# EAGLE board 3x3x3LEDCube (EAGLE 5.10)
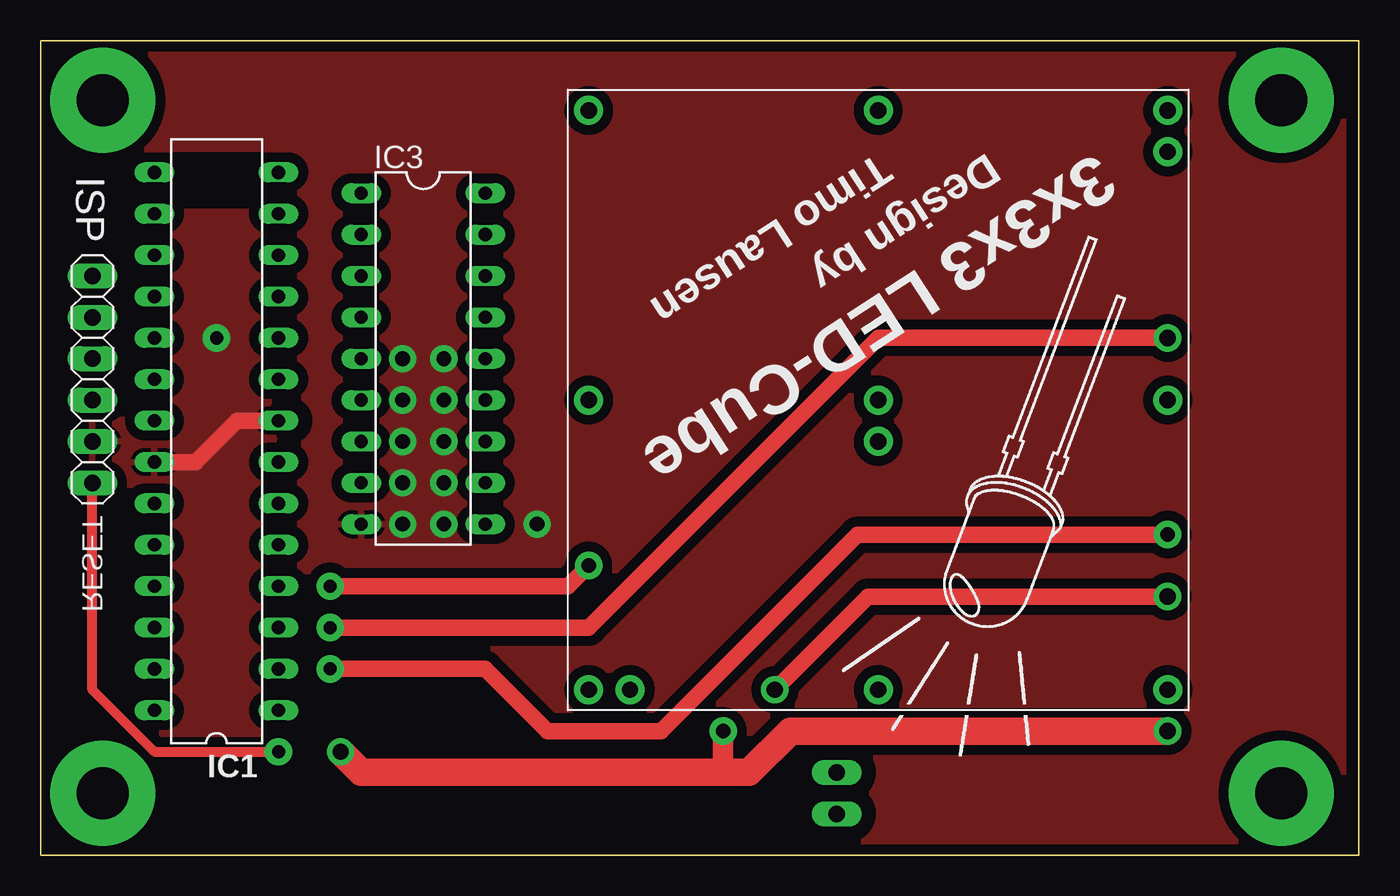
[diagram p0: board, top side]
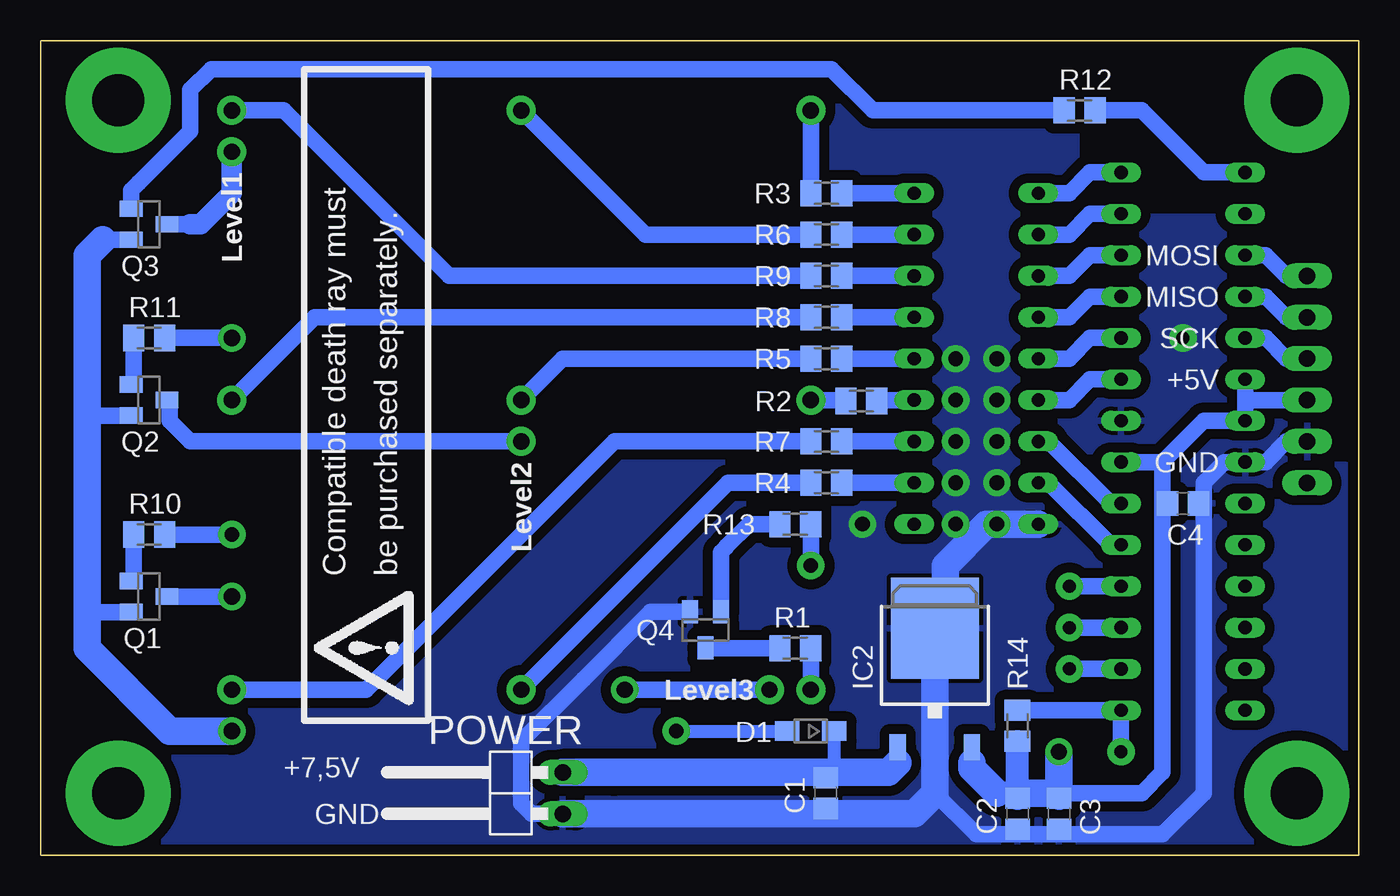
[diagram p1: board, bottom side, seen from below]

Size 80.95 x 50 mm. Coordinates in mm from the lower left corner, seen from the top.
Outline: 0,0 80,0
Outline: 80,50 0,50
Outline: 0,50 80.95,50 80.95,0 0,0
Outline: 0,0 0,50
Copper layers (1*2*15*16): Top 0.035mm / dielectric 0.2mm / Route2 0.0175mm / dielectric 1.1mm / Route15 0.0175mm / dielectric 0.2mm / Bottom 0.035mm
Design rules "SeeedStudio_DRU_no_angle_20130527 *": minimum track width 6mil, minimum drill 12mil, track to track 6mil, track to pad 6mil, pad to pad 6mil, via to via 6mil, smd to smd 0mil, copper to edge 10mil, drill to drill 10mil, minimum pad ring 6mil, minimum via ring 6mil, stop-mask expansion 2mil, vias tented up to drill 25mil, thermal gap 10mil
tRestrict: area 47.3,1.6 to 50.5,3.5; area 47.3,4.1 to 50.5,6; area 14.9,26 to 15.9,27.3; area 0.6,24.8 to 1.9,26; area 8.3,40.3 to 13.7,42.5
bRestrict: area 10.8,42.5 to 16.5,45.1; area 8.3,40 to 13.3,43.2; area 0.6,24.8 to 1.9,26

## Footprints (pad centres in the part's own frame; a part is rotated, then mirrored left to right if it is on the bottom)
C0805 = smd 1.3 x 1.5: 1 -0.95,0; 2 0.95,0
SOD323-W = smd 1.5 x 1.2: A 1.45,0; C -1.45,0
DIL28-3 = drill 0.813 long: 1 -16.51,-3.81; 2 -13.97,-3.81; 3 -11.43,-3.81; 4 -8.89,-3.81; 5 -6.35,-3.81; 6 -3.81,-3.81; 7 -1.27,-3.81; 8 1.27,-3.81; 9 3.81,-3.81; 10 6.35,-3.81; 11 8.89,-3.81; 12 11.43,-3.81; 13 13.97,-3.81; 14 16.51,-3.81; 15 16.51,3.81; 16 13.97,3.81; 17 11.43,3.81; 18 8.89,3.81; 19 6.35,3.81; 20 3.81,3.81; 21 1.27,3.81; 22 -1.27,3.81; 23 -3.81,3.81; 24 -6.35,3.81; 25 -8.89,3.81; 26 -11.43,3.81; 27 -13.97,3.81; 28 -16.51,3.81
TO252 = smd 1 x 1.6: 1 -2.28,-4.8; 2 2.28,-4.8 | smd 5.4 x 6.2: 3 0,2.5
DIL18 = drill 0.813 long: 1 -10.16,-3.81; 2 -7.62,-3.81; 3 -5.08,-3.81; 4 -2.54,-3.81; 5 0,-3.81; 6 2.54,-3.81; 7 5.08,-3.81; 8 7.62,-3.81; 9 10.16,-3.81; 10 10.16,3.81; 11 7.62,3.81; 12 5.08,3.81; 13 2.54,3.81; 14 0,3.81; 15 -2.54,3.81; 16 -5.08,3.81; 17 -7.62,3.81; 18 -10.16,3.81
1X06 = drill 1.016 long: 1 -6.35,0; 2 -3.81,0; 3 -1.27,0; 4 1.27,0; 5 3.81,0; 6 6.35,0
1X02/90 = drill 1.016 long: 1 -1.27,-3.81; 2 1.27,-3.81
SOT23 = smd 1 x 1.4: 1 -0.95,-1.1; 2 0.95,-1.1; 3 0,1.1
M0805 = smd 1.3 x 1.6: 1 -0.95,0; 2 0.95,0
CUBEPAD = drill 1 pad 1.778 round: EBENE1 2.54,0; EBENE2 17.78,15.24; EBENE3 35.56,33.02; LED1 0,0; LED2 0,17.78; LED3 0,35.56; LED4 17.78,0; LED5 17.78,17.78; LED6 17.78,35.56; LED7 35.56,0; LED8 35.56,17.78; LED9 35.56,35.56

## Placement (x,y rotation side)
C1  [C0805]  32.75,3.81 90 bottom
C2  [C0805]  20.95,2.54 90 bottom
C3  [C0805]  18.41,2.54 90 bottom
C4  100n  [C0805]  10.79,21.59 180 bottom
D1  1N4148  [SOD323-W]  33.66,7.62 180 bottom
IC1  MEGA8-P  [DIL28-3]  10.79,25.4 90 top
IC2  78M05  [TO252]  26.04,11.43 0 bottom
IC3  [DIL18]  23.5,30.48 270 top
ISP  [1X06]  3.17,29.21 270 top
POWER  [1X02/90]  52.7,3.81 90 bottom
Q1  SI2301  [SOT23]  74.3,15.88 270 bottom
Q2  SI2301  [SOT23]  74.3,27.94 270 bottom
Q3  SI2301  [SOT23]  74.3,38.73 270 bottom
Q4  IRLML 2502  [SOT23]  40.12,13.84 180 bottom
R1  [M0805]  34.61,12.7 180 bottom
R2  [M0805]  30.55,27.88 0 bottom
R3  [M0805]  32.7,40.64 0 bottom
R4  [M0805]  32.7,22.86 0 bottom
R5  [M0805]  32.7,30.48 0 bottom
R6  [M0805]  32.7,38.1 0 bottom
R7  [M0805]  32.7,25.4 0 bottom
R8  [M0805]  32.7,33.02 0 bottom
R9  [M0805]  32.7,35.56 0 bottom
R10  330R  [M0805]  74.3,19.68 0 bottom
R11  330R  [M0805]  74.3,31.75 0 bottom
R12  330R  [M0805]  17.14,45.72 0 bottom
R13  330R  [M0805]  34.61,20.32 0 bottom
R14  [M0805]  20.95,7.94 270 bottom
U$1  3X3X3LEDCUBE  [CUBEPAD]  33.66,10.16 0 top

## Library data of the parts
C1-C4 R1-R14 = rcl
D1 = diode
IC1 = atmel
IC2 = linear
IC3 = uln-udn
ISP POWER = pinhead
Q1-Q4 = transistor-small-signal
U$1 = zeug

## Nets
0V: C1.1 C2.1 C3.1 C4.1 IC1.8 IC1.22 IC2.3 IC3.9 ISP.5 POWER.1 Q4.2
+5V: C2.2 C3.2 C4.2 D1.A IC1.7 IC1.20 IC1.21 IC2.2 ISP.4 Q1.2 Q2.2 Q3.2 R14.2
CON_MISO: IC1.18 ISP.2
CON_MOSI: IC1.17 ISP.1
CON_RESET: IC1.1 ISP.6 R14.1
CON_SCK: IC1.19 ISP.3
DRAIN: Q4.3 R1.2
EBENE1: IC1.2 R10.2
EBENE2: IC1.3 R11.2
EBENE3: IC1.15 R12.2
GATE: Q4.1 R13.1
LED1: IC1.4 R13.2
LED2: IC1.9 IC3.6
LED3: IC1.14 IC3.1
LED4: IC1.5 IC3.8
LED5: IC1.10 IC3.5
LED6: IC1.13 IC3.2
LED7: IC1.6 IC3.7
LED8: IC1.11 IC3.4
LED9: IC1.12 IC3.3
N$1: Q1.3 U$1.EBENE1
N$2: Q2.3 U$1.EBENE2
N$3: Q3.3 U$1.EBENE3
N$4: IC3.15 R8.2
N$5: IC3.18 R3.2
N$6: IC3.17 R6.2
N$7: IC3.16 R9.2
N$8: IC3.13 R2.2
N$9: IC3.14 R5.2
N$10: IC3.12 R7.2
N$11: R1.1 U$1.LED1
N$16: IC3.11 R4.2
N$23: Q3.1 R12.1
N$24: Q2.1 R11.1
N$25: Q1.1 R10.1
N$32: R2.1 U$1.LED2
N$33: C1.2 D1.C IC2.1 POWER.2
N$34: R3.1 U$1.LED3
N$35: R4.1 U$1.LED4
N$36: R5.1 U$1.LED5
N$37: R6.1 U$1.LED6
N$38: R7.1 U$1.LED7
N$39: R8.1 U$1.LED8
N$40: R9.1 U$1.LED9

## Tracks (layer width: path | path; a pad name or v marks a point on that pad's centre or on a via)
0V  (via drill 0.8 pad 1.68, 0.9 pad 1.68)
  Top 1.016: IC1.8 12.06,26.67 9.53,24.13 IC1.22
  Bottom 0.406: 16.51,1.27 15.24,1.27
  Bottom 1.016: ISP.5 4.45,25.4 5.71,24.13 IC1.22 8.26,24.13 9.53,22.86 9.53,21.59 | 26.04,3.81 23.5,1.27 20.95,1.27 | 18.41,1.27 16.51,1.27 12.06,1.27 9.53,3.81 9.53,21.59 | 18.41,1.27 20.95,1.27 | 25.4,15.88 26.04,15.88 | 9.53,21.59 C4.1 | 18.41,1.27 C3.1 | 20.95,1.27 C2.1 | IC2.3 26.07,13.97 | Q4.2 43.48,14.94 47.62,10.79 51.44,6.99 51.44,3.17 50.8,2.54 POWER.1
  Bottom 1.27: C1.1 32.7,2.86 32.38,2.54
  Bottom 1.422: IC2.3 25.4,15.88
  Bottom 1.676: 25.4,15.88 25.4,17.78 22.86,20.32 v22.23,20.32 IC3.9 | IC2.3 26.04,3.81 27.3,2.54 32.38,2.54 45.72,2.54 POWER.1
  other vias: 24.77,20.32 22.23,25.4 24.77,25.4 22.23,22.86 24.77,22.86 30.48,20.32 22.23,27.94 24.77,27.94 22.23,30.48 24.77,30.48 10.79,31.75
  pour Bottom (isolate 0.61): 0,0 80.01,0 80.01,50.16 0,50.16
  pour Top (isolate 0.61): 0,50.16 80.01,50.16 80.01,0 0,0
+5V  (via drill 0.9 pad 1.68, 1 pad 1.68)
  Top 1.27: v41.91,7.62 41.91,6.67 41.91,5.08
  Top 1.676: v69.22,7.62 46.04,7.62 43.5,5.08 41.91,5.08 19.68,5.08 v18.41,6.35
  Bottom 0.254: 12.06,21.59 C4.2
  Bottom 0.813: v41.91,7.62 D1.A
  Bottom 1.016: 23.75,5.66 IC2.2 | 18.41,3.81 15.24,3.81 13.34,3.81 12.06,5.08 12.06,21.59 12.06,24.13 | 12.06,24.13 IC1.7 | 12.06,24.13 9.53,26.67 IC1.21 6.99,27.94 | 6.99,27.94 IC1.20 | 6.99,27.94 ISP.4 | 77.15,37.78 Q3.2 | Q2.2 78.11,26.99 78.11,27.94 | Q1.2 78.11,14.93 78.11,15.24
  Bottom 1.422: R14.2 C2.2 21.27,3.81 22.23,3.81 | 18.41,3.81 C3.2
  Bottom 1.676: 21.27,3.81 18.41,3.81 v18.41,6.35 | 23.75,5.66 23.75,5.34 22.23,3.81 | v69.22,7.62 73.03,7.62 78.11,12.7 78.11,15.24 78.11,27.94 78.11,34.29 78.11,36.2 78.11,36.83 77.15,37.78
CON_MISO
  Bottom 1.016: IC1.18 5.71,34.29 4.45,33.02 ISP.2
CON_MOSI
  Bottom 1.016: IC1.17 5.71,36.83 4.45,35.56 ISP.1
CON_RESET  (via drill 0.8 pad 1.68)
  Top 0.61: ISP.6 3.17,10.16 6.99,6.35 v14.61,6.35
  Bottom 0.61: R14.1
  Bottom 0.813: R14.1
  Bottom 1.016: R14.1 IC1.1 v14.61,6.35
CON_SCK
  Bottom 1.016: IC1.19 5.71,31.75 4.45,30.48 ISP.3
DRAIN
  Bottom 1.016: R1.2 38.1,12.7 40.12,12.7 Q4.3
EBENE1  (via drill 0.8 pad 1.68, 0.9 pad 1.68)
  Top 1.016: v69.22,19.68 50.16,19.68 38.1,7.62 31.11,7.62 27.3,11.43 v17.78,11.43
  Bottom 1.016: v69.22,19.68 R10.2 | IC1.2 v17.78,11.43
EBENE2  (via drill 0.8 pad 1.68, 1 pad 1.68)
  Top 1.016: v17.78,13.97 33.66,13.97 51.44,31.75 v69.22,31.75
  Bottom 1.016: v69.22,31.75 R11.2 | IC1.3 v17.78,13.97
EBENE3
  Bottom 1.016: IC1.15 9.53,41.91 13.34,45.72 R12.2
GATE
  Bottom 1.016: R13.1 37.47,20.32 38.83,18.95 38.88,18.91 39.17,18.61 Q4.1
LED1  (via drill 0.8 pad 1.68, 0.9 pad 1.68)
  Top 1.016: v33.66,17.78 32.38,16.51 v17.78,16.51
  Bottom 1.016: v33.66,17.78 R13.2 | IC1.4 v17.78,16.51
LED2
  Bottom 1.016: IC1.9 16.51,29.21 17.78,27.94 IC3.6
LED3
  Bottom 1.016: IC1.14 16.51,41.91 17.78,40.64 IC3.1
LED4
  Bottom 1.016: IC1.5 15.24,19.05 19.05,22.86 20.32,22.86 IC3.8
LED5
  Bottom 1.016: IC1.10 16.51,31.75 17.78,30.48 IC3.5
LED6
  Bottom 1.016: IC1.13 16.51,39.37 17.78,38.1 IC3.2
LED7
  Bottom 1.016: IC1.6 15.24,21.59 19.05,25.4 IC3.7
LED8
  Bottom 1.016: IC1.11 16.51,34.29 17.78,33.02 IC3.4
LED9
  Bottom 1.016: IC1.12 16.51,36.83 17.78,35.56 IC3.3
N$1  (via drill 1 pad 1.68)
  Top 1.016: v69.22,15.88 50.8,15.88 v45.09,10.16
  Bottom 1.016: U$1.EBENE1 v45.09,10.16 | v69.22,15.88 Q1.3
N$2
  Bottom 1.016: U$1.EBENE2 71.75,25.4 73.03,26.67 73.03,27.94 Q2.3
N$3
  Bottom 1.016: 71.75,38.73 Q3.3
  Bottom 1.27: U$1.EBENE3 69.22,40.64 70.48,39.37 71.12,38.73 71.75,38.73
N$4
  Bottom 1.016: IC3.15 R8.2
N$5
  Bottom 1.016: IC3.18 R3.2
N$6
  Bottom 1.016: IC3.17 R6.2
N$7
  Bottom 1.016: IC3.16 R9.2
N$8
  Bottom 1.016: IC3.13 29.74,27.94 R2.2
N$9
  Bottom 1.016: IC3.14 R5.2
N$10
  Bottom 1.016: IC3.12 R7.2
N$11
  Bottom 1.016: R1.1 U$1.LED1
N$12  (via drill 3.2 pad 6.45)
  other vias: 3.81,46.35
N$13  (via drill 3.2 pad 6.45)
  other vias: 76.2,46.35
N$14  (via drill 3.2 pad 6.45)
  other vias: 76.2,3.81
N$15  (via drill 3.2 pad 6.45)
  other vias: 3.81,3.81
N$16
  Bottom 1.016: IC3.11 R4.2
N$23
  Bottom 1.016: R12.1 29.84,45.72 32.38,48.26 70.48,48.26 71.75,46.99 71.75,44.45 74.93,41.27 75.39,40.81 Q3.1
N$24
  Bottom 1.016: R11.1 75.25,28.89 Q2.1
N$25
  Bottom 1.016: R10.1 75.25,16.82 Q1.1
N$32
  Bottom 1.016: R2.1 31.76,27.94 U$1.LED2
N$33
  Bottom 0.406: 28.32,5.66 IC2.1
  Bottom 0.813: D1.C 32.2,5.08 31.11,5.08
  Bottom 1.016: IC2.1 28.32,6.29
  Bottom 1.27: C1.2 32.75,4.81 33.02,5.08
  Bottom 1.676: 28.32,5.66 28.89,5.08 31.11,5.08 31.75,5.08 33.02,5.08 45.72,5.08 POWER.2
N$34
  Bottom 1.016: R3.1 U$1.LED3
N$35
  Bottom 1.016: R4.1 38.73,22.86 U$1.LED4
N$36
  Bottom 1.016: R5.1 48.9,30.48 U$1.LED5
N$37
  Bottom 1.016: R6.1 43.81,38.1 U$1.LED6
N$38
  Bottom 1.016: R7.1 45.72,25.4 60.96,10.16 U$1.LED7
N$39
  Bottom 1.016: R8.1 64.14,33.02 U$1.LED8
N$40
  Bottom 1.016: U$1.LED9 66.04,45.72 55.88,35.56 R9.1

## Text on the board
bPlace: Level1 | Level2 | be purchased separately. | Compatible death ray must | Level3
tNames: Timo Lausen | Design by | 3x3x3 LED-Cube | RESET
bNames: MOSI | MISO | SCK | +5V | GND | +7,5V | GND
Document: Anmerkung: | - Vias unter IC3 dienen der Wärmeableitung, wird die Platine selbst geätzt, müssen diese nicht durchkontaktiert werden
